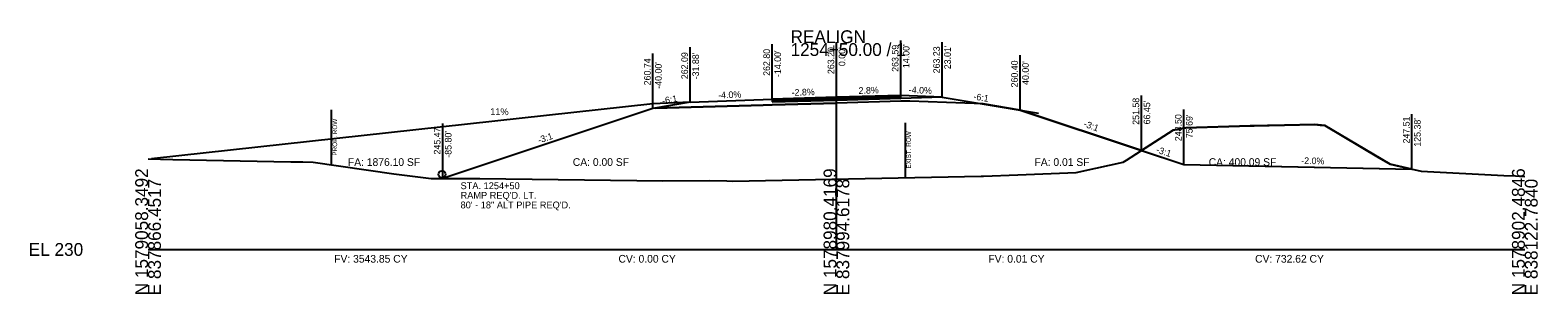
# Model space of a CAD drawing. Extents: x -26 to 6303, y -16 to 9563.
# Drawn here: x 2974.3 to 3302.8, y 6490.3 to 6547.8 of the extents above; entities that cross this region are included whole.
import ezdxf

# ---------------------------------------------------------------- set-up
doc = ezdxf.new("R2010")
doc.units = 0
for name, color, linetype in [('ASPHALT_19MM1', 7, 'Continuous'), ('ASPHALT_9_5MM1', 7, 'Continuous'), ('CONST_LV3', 7, 'Continuous'), ('CONST_PROF_LV1', 7, 'Continuous'), ('Draft_XS_Grid', 7, 'Continuous'), ('DTM_TEMP_DROP', 7, 'Continuous'), ('DTM_X_FLOW_ARROWS', 7, 'Continuous'), ('DTM_X_GROUND', 7, 'Continuous'), ('TRANS_BRIDGE', 7, 'Continuous'), ('XS_CELL', 7, 'Continuous'), ('XS_M_SHAPES_EARTHWORK', 7, 'Continuous'), ('XS_P_DRAINAGE', 7, 'Continuous'), ('XS_P_DRIVEWAY', 7, 'Continuous'), ('XS_P_GROUND', 7, 'Continuous'), ('XS_P_NULL_POINT', 7, 'Continuous'), ('XS_P_ROW', 7, 'Continuous'), ('XS_P_SHOULDER', 7, 'Continuous'), ('XS_P_SUBGRADE_GRANULAR', 7, 'Continuous'), ('XS_P_TX_CLEARZONE', 7, 'Continuous'), ('XS_P_TX_FS_BS', 7, 'Continuous'), ('XS_PLAN_CLEAR_ZONE', 7, 'Continuous'), ('XS_SHEET_EW_TX_AREA', 7, 'Continuous'), ('XS_SHEET_EW_TX_VOLUME', 7, 'Continuous'), ('XS_X_ROW', 7, 'Continuous')]:
    doc.layers.add(name, color=color, linetype=linetype)

msp = doc.modelspace()

# ---------------------------------------------------------------- linework, layer by layer
at = {"layer": 'ASPHALT_19MM1'}
msp.add_lwpolyline([(3136, 6532.2), (3136, 6532.2), (3136, 6532.2), (3150, 6532.59), (3150, 6532.59), (3164, 6532.98), (3164, 6532.98), (3164, 6533.26), (3150, 6532.86), (3150, 6532.86), (3136, 6532.47), (3136, 6532.47), (3136, 6532.2)], dxfattribs=at)
at = {"layer": 'ASPHALT_9_5MM1'}
msp.add_lwpolyline([(3136, 6532.68), (3136, 6532.68), (3136, 6532.68), (3150, 6533.07), (3150, 6533.07), (3164, 6533.46), (3164, 6533.46), (3164, 6533.59), (3150, 6533.2), (3150, 6533.2), (3136, 6532.8), (3136, 6532.8), (3136, 6532.68)], dxfattribs=at)
at = {"layer": 'CONST_LV3'}
for points in [[(3150, 6533.2), (3164, 6532.92)], [(3173.01, 6533.23), (3164, 6532.92), (3164, 6532.92)], [(3181.97, 6531.73), (3194, 6529.73)], [(3110.51, 6530.82), (3110, 6530.74)]]:
    msp.add_lwpolyline(points, dxfattribs=at)
at = {"layer": 'DTM_X_GROUND'}
msp.add_lwpolyline([(3000, 6519.76), (3005.39, 6519.63), (3031.13, 6519.13), (3031.92, 6519.12), (3033.69, 6519.08), (3035.97, 6519.04), (3053.55, 6516.52), (3061.69, 6515.46), (3066.9, 6515.48), (3072.31, 6515.49), (3112.19, 6514.98), (3122.27, 6515.02), (3126.1, 6514.94), (3127.38, 6514.92), (3181.55, 6515.95), (3181.8, 6515.96), (3181.87, 6515.97), (3182.08, 6515.97), (3189.55, 6516.27), (3202.26, 6516.78), (3206.55, 6517.73), (3212.45, 6519.03), (3213.18, 6519.49), (3223.39, 6526.01), (3226.06, 6526.55), (3226.08, 6526.55), (3226.17, 6526.56), (3240.14, 6526.97), (3241.03, 6526.99), (3254.27, 6527.25), (3255.4, 6527.13), (3256.44, 6527.03), (3268.12, 6520.07), (3270.64, 6518.57), (3271.89, 6518.29), (3277.45, 6517.04), (3295.42, 6516.14), (3297.99, 6516.03), (3298.81, 6515.99), (3300, 6515.93)], dxfattribs=at)
at = {"layer": 'XS_CELL'}
for p, q in [((3150, 6500), (3150, 6545)), ((3000, 6500), (3150, 6500)), ((3150, 6500), (3300, 6500))]:
    msp.add_line(p, q, dxfattribs=at)
at = {"layer": 'XS_M_SHAPES_EARTHWORK'}
msp.add_lwpolyline([(3064.2, 6515.47), (3066.9, 6515.48), (3072.31, 6515.49), (3112.19, 6514.98), (3122.27, 6515.02), (3126.1, 6514.94), (3127.38, 6514.92), (3181.55, 6515.95), (3181.8, 6515.96), (3181.87, 6515.97), (3182.08, 6515.97), (3189.55, 6516.27), (3202.26, 6516.78), (3206.55, 6517.73), (3212.45, 6519.03), (3213.18, 6519.49), (3216.45, 6521.58), (3190, 6530.4), (3181.97, 6531.73), (3166, 6532.37), (3164, 6532.32), (3150, 6531.93), (3136, 6531.53), (3134, 6531.48), (3110.51, 6530.82), (3110, 6530.74)], close=True, dxfattribs=at)
at = {"layer": 'XS_P_DRAINAGE'}
msp.add_circle((3064.05, 6516.37), 0.75, dxfattribs=at)
at = {"layer": 'XS_P_DRIVEWAY'}
for p, q in [((3110, 6531.76), (3000.72, 6519.74)), ((3118.12, 6532.09), (3110, 6531.76))]:
    msp.add_line(p, q, dxfattribs=at)
at = {"layer": 'XS_P_GROUND'}
for points in [[(3118.12, 6532.09), (3110, 6530.74), (3064.2, 6515.47)], [(3173.01, 6533.23), (3190, 6530.4), (3216.45, 6521.58)], [(3173.01, 6533.23), (3190, 6530.4), (3225.69, 6518.5)], [(3225.69, 6518.5), (3240.03, 6518.21)], [(3240.03, 6518.21), (3275.38, 6517.51)]]:
    msp.add_lwpolyline(points, dxfattribs=at)
at = {"layer": 'XS_P_ROW'}
msp.add_line((3040, 6518.46), (3040, 6530.46), dxfattribs=at)
at = {"layer": 'XS_P_SHOULDER'}
for points in [[(3118.12, 6532.09), (3136, 6532.8), (3136, 6532.8)], [(3173.01, 6533.23), (3164, 6533.59), (3164, 6533.59)]]:
    msp.add_lwpolyline(points, dxfattribs=at)
at = {"layer": 'XS_P_SUBGRADE_GRANULAR'}
for points in [[(3110.51, 6530.82), (3134, 6531.48), (3134, 6531.48), (3134, 6531.48), (3136, 6531.53)], [(3136, 6531.53), (3136, 6531.53), (3150, 6531.93)], [(3164, 6532.32), (3150, 6531.93), (3150, 6531.93)], [(3181.97, 6531.73), (3166, 6532.37), (3166, 6532.37), (3164, 6532.32), (3164, 6532.32)]]:
    msp.add_lwpolyline(points, dxfattribs=at)
at = {"layer": 'XS_P_TX_CLEARZONE'}
for p, q in [((3136, 6532.8), (3136, 6544.8)), ((3150, 6533.2), (3150, 6545.2)), ((3164, 6533.59), (3164, 6545.59)), ((3173.01, 6533.23), (3173.01, 6545.23)), ((3173.01, 6533.23), (3173.01, 6545.23)), ((3110, 6530.74), (3110, 6542.74)), ((3118.12, 6532.09), (3118.12, 6544.09)), ((3190, 6530.4), (3190, 6542.4)), ((3216.45, 6521.58), (3216.45, 6533.58)), ((3225.69, 6518.5), (3225.69, 6530.5)), ((3275.38, 6517.51), (3275.38, 6529.51)), ((3064.2, 6515.47), (3064.2, 6527.47))]:
    msp.add_line(p, q, dxfattribs=at)
at = {"layer": 'XS_P_TX_FS_BS'}
msp.add_lwpolyline([(3216.45, 6521.58), (3225.69, 6518.5), (3275.38, 6517.51), (3270.64, 6518.57), (3256.44, 6527.03), (3254.27, 6527.25), (3247.65, 6527.12), (3240.14, 6526.97), (3233.15, 6526.76), (3226.17, 6526.56), (3223.39, 6526.01)], close=True, dxfattribs=at)
at = {"layer": 'XS_PLAN_CLEAR_ZONE'}
msp.add_lwpolyline([(3136, 6532.47), (3136, 6532.47), (3136, 6532.47), (3150, 6532.86), (3150, 6532.86), (3164, 6533.26), (3164, 6533.26), (3164, 6533.46), (3150, 6533.07), (3150, 6533.07), (3136, 6532.68), (3136, 6532.68), (3136, 6532.47)], dxfattribs=at)
at = {"layer": 'XS_X_ROW'}
msp.add_line((3165.03, 6515.64), (3165.03, 6527.64), dxfattribs=at)

# ---------------------------------------------------------------- texts
at = {"layer": 'CONST_PROF_LV1'}
for p in [(3216.37, 6521.46), (3064.12, 6515.35)]:
    msp.add_text('X', height=0.24, dxfattribs=at).set_placement(p)
at = {"layer": 'Draft_XS_Grid'}
msp.add_text('-', height=0.0001, dxfattribs=at).set_placement((3000, 6500))
at = {"layer": 'DTM_TEMP_DROP'}
for p in [(3135.92, 6532.68), (3149.92, 6533.08), (3163.92, 6533.47)]:
    msp.add_text('X', height=0.24, dxfattribs=at).set_placement(p)
at = {"layer": 'DTM_X_FLOW_ARROWS'}
msp.add_text('X', height=0.24, dxfattribs=at).set_placement((3275.31, 6517.39))
at = {"layer": 'TRANS_BRIDGE'}
for p in [(3216.37, 6521.46), (3064.12, 6515.35)]:
    msp.add_text('X', height=0.24, dxfattribs=at).set_placement(p)
at = {"layer": 'XS_CELL'}
for s, p in [('REALIGN', (3140, 6545)), ('1254+50.00 / 1', (3140, 6542.2)), ('EL 230', (2974, 6498.6))]:
    msp.add_text(s, height=2.8, dxfattribs=at).set_placement(p)
for s, p in [('N 1579058.3492', (3000, 6490)), ('E 837866.4517', (3002.8, 6490)), ('N 1578980.4169', (3150, 6490)), ('E 837994.6178', (3152.8, 6490)), ('N 1578902.4846', (3300, 6490)), ('E 838122.7840', (3302.8, 6490))]:
    msp.add_text(s, height=2.8, rotation=90, dxfattribs=at).set_placement(p)
at = {"layer": 'XS_P_DRIVEWAY'}
for s, p in [('11%', (3074.55, 6529.3)), ('STA. 1254+50', (3068.1, 6513.15)), ("RAMP REQ'D. LT.", (3068.1, 6511.05)), ('80\' - 18" ALT PIPE REQ\'D.', (3068.1, 6508.95))]:
    msp.add_text(s, height=1.5, dxfattribs=at).set_placement(p)
at = {"layer": 'XS_P_GROUND'}
for p in [(3109.92, 6530.62), (3193.92, 6529.61)]:
    msp.add_text('X', height=0.24, dxfattribs=at).set_placement(p)
at = {"layer": 'XS_P_NULL_POINT'}
for p in [(3172.93, 6533.11), (3189.92, 6530.28)]:
    msp.add_text('X', height=0.24, dxfattribs=at).set_placement(p)
at = {"layer": 'XS_P_ROW'}
msp.add_text('PROP. ROW', height=1, rotation=90, dxfattribs=at).set_placement((3041.2, 6520.46))
at = {"layer": 'XS_P_SHOULDER'}
for p in [(3118.04, 6531.97), (3172.93, 6533.11)]:
    msp.add_text('X', height=0.24, dxfattribs=at).set_placement(p)
at = {"layer": 'XS_P_SUBGRADE_GRANULAR'}
msp.add_text('X', height=0.24, dxfattribs=at).set_placement((3225.61, 6518.38))
at = {"layer": 'XS_P_TX_CLEARZONE'}
for s, p in [('263.59', (3163.52, 6538.75)), ("14.00'", (3165.92, 6539.56)), ("23.01'", (3174.93, 6539.31)), ('260.74', (3109.52, 6535.8)), ('262.09', (3117.64, 6537.14)), ("-31.88'", (3120.04, 6537.11)), ('262.80', (3135.52, 6537.86)), ("-14.00'", (3137.92, 6537.6)), ('263.20', (3149.52, 6538.25)), ("0.00'", (3151.92, 6539.98)), ('263.23', (3172.53, 6538.41)), ('260.40', (3189.52, 6535.34)), ("-40.00'", (3111.92, 6535.05)), ("40.00'", (3191.92, 6535.89)), ('251.58', (3215.97, 6527.19)), ("66.45'", (3218.37, 6527.28)), ('248.50', (3225.21, 6523.62)), ("75.69'", (3227.61, 6524.27)), ('247.51', (3274.9, 6523.11)), ("125.38'", (3277.3, 6522.41)), ('245.47', (3063.72, 6520.71)), ("-85.80'", (3066.12, 6520.01))]:
    msp.add_text(s, height=1.44, rotation=90, dxfattribs=at).set_placement(p)
at = {"layer": 'XS_P_TX_FS_BS'}
for s, rotation, p in [('-4.0%', 2.2906, (3124.25, 6532.93)), ('-2.8%', 1.6039, (3140.25, 6533.52)), ('2.8%', 1.6039, (3154.84, 6533.93)), ('-4.0%', 357.7094, (3165.74, 6534.12)), ('-6:1', 9.4642, (3112.14, 6531.7)), ('-6:1', 350.5377, (3179.78, 6532.71)), ('-3:1', 18.4332, (3085.19, 6523.1)), ('-3:1', 340.05, (3203.73, 6526.84)), ('-3:1', 341.5634, (3219.54, 6521.18)), ('-2.0%', 358.8542, (3251.27, 6518.66))]:
    msp.add_text(s, height=1.44, rotation=rotation, dxfattribs=at).set_placement(p)
at = {"layer": 'XS_SHEET_EW_TX_AREA'}
for s, p in [('FA: 1876.10 SF', (3043.55, 6518.22)), ('CA: 0.00 SF', (3092.56, 6518.22)), ('FA: 0.01 SF', (3193.16, 6518.22)), ('CA: 400.09 SF', (3231.12, 6518.22))]:
    msp.add_text(s, height=1.68, dxfattribs=at).set_placement(p)
at = {"layer": 'XS_SHEET_EW_TX_VOLUME'}
for s, p in [('FV: 3543.85 CY', (3040.56, 6497.12)), ('CV: 0.00 CY', (3102.51, 6497.12)), ('FV: 0.01 CY', (3183.11, 6497.12)), ('CV: 732.62 CY', (3241.23, 6497.12))]:
    msp.add_text(s, height=1.68, dxfattribs=at).set_placement(p)
at = {"layer": 'XS_X_ROW'}
msp.add_text('EXIST. ROW', height=1, rotation=90, dxfattribs=at).set_placement((3166.23, 6517.64))

doc.saveas('drawing.dxf')
